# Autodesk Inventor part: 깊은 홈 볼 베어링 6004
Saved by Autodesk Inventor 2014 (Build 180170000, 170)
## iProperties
Created: 2026-04
Part Number: 깊은 홈 볼 베어링 6004
Material: 일반
Document SubType Name: Modeling
Designer: dg
Density: 1 g/cm^3
Appearance: 기본값
Author: dg
Author: jhkim
Description: 깊은 그루브 볼 베어링
Creation Date: 2026-03-26
Sending System: Autodesk Inventor 2026
Preprocessor: ST-DEVELOPER v20.1
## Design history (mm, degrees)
node "깊은 홈 볼 베어링 60041"
body "Solid1"
node "Solid1_1"
node "Solid1_2"
node "Solid1_3"
node "Solid1_4"
node "Solid1_5"
node "Solid1_6"
node "Solid1_7"
node "Solid1_8"
node "Solid1_9"
node "Solid1_10"
node "기준1"
node "기준2"
node "기준3"
node "기준4"
node "기준5"
node "기준6"
node "기준7"
node "기준8"
node "기준9"
node "기준10"
node "기준11"
